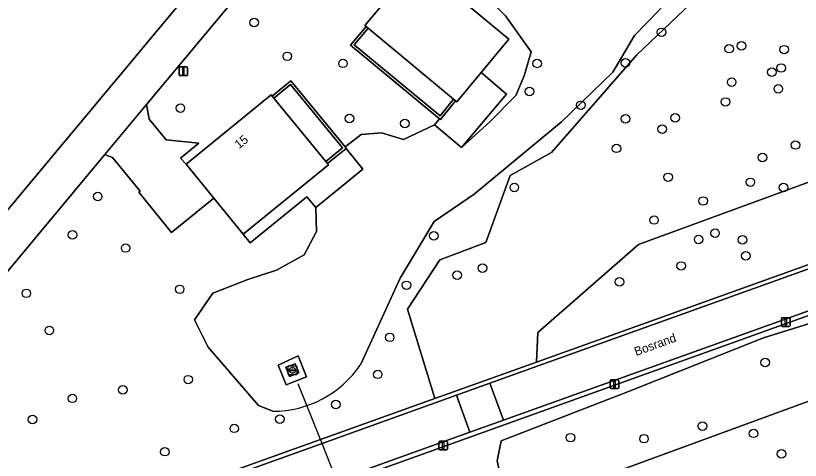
# Model space of a CAD drawing. Extents: x 156661 to 157576, y 383570 to 384425.
# Drawn here: x 156996.3 to 157086.2, y 383757.3 to 383808.2 of the extents above; entities that cross this region are included whole.
import ezdxf

# ---------------------------------------------------------------- set-up
doc = ezdxf.new("R2010")
doc.units = 0
for name, color, linetype in [('IMGEO_Boom', 7, 'Continuous'), ('IMGEO_Duiker', 7, 'Continuous'), ('IMGEO_Erf', 7, 'Continuous'), ('IMGEO_Groenvoorziening', 7, 'Continuous'), ('IMGEO_Kolk', 7, 'Continuous'), ('IMGEO_Lichtmast', 7, 'Continuous'), ('IMGEO_Loofbos', 7, 'Continuous'), ('IMGEO_Meer_plas_ven_vijver', 7, 'Continuous'), ('IMGEO_Muur', 7, 'Continuous'), ('IMGEO_Openbare_ruimte_label', 7, 'Continuous'), ('IMGEO_Pand', 7, 'Continuous'), ('IMGEO_Pand_nummerreeks', 7, 'Continuous'), ('IMGEO_Rijbaan_lokaal_halfverhard', 7, 'Continuous'), ('IMGEO_Rijbaan_lokaal_open', 7, 'Continuous'), ('IMGEO_Terreindeel_halfverhard', 7, 'Continuous'), ('IMGEO_Terreindeel_open', 7, 'Continuous')]:
    doc.layers.add(name, color=color, linetype=linetype)

msp = doc.modelspace()

# ---------------------------------------------------------------- linework, layer by layer
at = {"layer": 'IMGEO_Boom'}
for centre in [(157023.586, 383807.399), (157070.266, 383806.274), (157078.003, 383804.396), (157079.431, 383804.722), (157027.378, 383803.523), (157084.32, 383804.288), (157033.761, 383802.717), (157056.017, 383802.713), (157066.138, 383802.772), (157082.896, 383801.711), (157083.961, 383802.188), (157078.297, 383800.559), (157083.643, 383799.808), (157055.136, 383799.494), (157077.593, 383798.295), (157015.127, 383797.576), (157061.008, 383797.913), (157034.497, 383796.409), (157066.128, 383796.361), (157071.829, 383796.469), (157040.851, 383795.831), (157070.321, 383795.171), (157065.097, 383792.979), (157085.608, 383793.361), (157081.831, 383791.924), (157071.017, 383789.666), (157080.441, 383789.096), (157053.394, 383788.501), (157084.233, 383788.488), (157005.654, 383787.467), (157075.021, 383786.954), (157069.402, 383784.773), (157002.775, 383783.072), (157044.176, 383782.955), (157076.391, 383783.263), (157074.509, 383782.544), (157079.541, 383782.504), (157008.854, 383781.564), (157079.93, 383780.668), (157049.75, 383779.249), (157072.508, 383779.515), (157046.842, 383778.451), (157065.44, 383777.699), (157015.053, 383776.838), (157041.044, 383777.301), (156997.479, 383776.378), (157000.113, 383772.115), (157039.116, 383771.338), (157082.143, 383768.453), (157037.741, 383767.098), (157016.033, 383766.494), (157008.524, 383765.317), (157002.754, 383764.348), (157032.946, 383763.648), (156998.183, 383761.932), (157026.518, 383761.972), (157074.961, 383761.159), (157021.308, 383760.914), (157080.791, 383760.337), (157059.835, 383759.848), (157068.257, 383759.732), (157013.341, 383758.239), (157084.013, 383758.006)]:
    msp.add_circle(centre, 0.489, dxfattribs=at)
at = {"layer": 'IMGEO_Duiker'}
msp.add_lwpolyline([(157036.031, 383747.459), (157035.68, 383748.34), (157035.126, 383749.729), (157033.227, 383754.492), (157033.035, 383754.973), (157031.359, 383759.177), (157031.176, 383759.637), (157028.632, 383766.018)], dxfattribs=at)
at = {"layer": 'IMGEO_Erf'}
for points in [[(157036.639, 383806.758), (157035.055, 383804.855), (157044.899, 383796.693), (157046.433, 383798.607)], [(157049.612, 383801.681), (157046.791, 383798.309), (157046.66, 383798.418), (157044.942, 383796.275), (157044.832, 383796.367), (157044.237, 383795.66), (157047.355, 383793.093), (157052.489, 383799.189)], [(157025.835, 383798.749), (157031.798, 383791.459), (157033.713, 383793.026), (157027.752, 383800.314)], [(157015.787, 383791.168), (157015.141, 383791.863), (157017.237, 383793.583), (157013.515, 383793.948), (157011.55, 383796.328), (157011.25, 383798.001), (157006.477, 383792.278), (157006.733, 383792.178), (157007.366, 383791.931), (157010.536, 383788.085), (157010.387, 383787.957), (157014.101, 383783.353), (157018.957, 383787.281)], [(157034.129, 383792.985), (157031.985, 383791.231), (157032.093, 383791.1), (157022.328, 383783.148), (157023.125, 383782.171), (157029.603, 383787.444), (157030.634, 383786.19), (157036.05, 383790.598)]]:
    msp.add_lwpolyline(points, close=True, dxfattribs=at)
at = {"layer": 'IMGEO_Groenvoorziening'}
for points in [[(157001.056, 383748.839), (157031.176, 383759.637), (157044.279, 383764.335), (157041.161, 383774.554), (157044.855, 383780.228), (157050.132, 383782.207), (157052.903, 383789.859), (157057.653, 383792.498), (157067.416, 383803.713), (157075.201, 383811.102), (157078.499, 383816.907), (157083.249, 383825.483), (157079.423, 383827.99), (157075.729, 383832.476), (157070.319, 383836.83), (157065.701, 383839.6), (157058.84, 383842.107), (157053.931, 383851.225)], [(156977.657, 383765.109), (156984.098, 383772.514), (157042.748, 383842.776), (157045.986, 383846.984)], [(157033.585, 383824.777), (157011.25, 383798.001), (157011.55, 383796.328), (157013.515, 383793.948), (157017.237, 383793.583), (157015.141, 383791.863), (157015.787, 383791.168), (157025.541, 383799.109), (157025.648, 383798.977), (157027.792, 383800.731), (157033.993, 383793.151), (157035.856, 383794.566), (157038.179, 383794.751), (157040.685, 383794.008), (157044.237, 383795.66), (157044.832, 383796.367), (157034.639, 383804.817), (157036.412, 383806.947), (157036.281, 383807.055), (157038.979, 383810.3)], [(157048.157, 383809.325), (157052.782, 383805.471), (157049.612, 383801.681), (157052.489, 383799.189), (157047.355, 383793.093), (157050.592, 383796.034), (157053.555, 383799.055), (157054.51, 383801.302), (157055.329, 383804.054), (157052.364, 383808.162), (157049.338, 383811.217)], [(157069.849, 383808.66), (157067.156, 383805.908), (157064.689, 383801.724), (157058.8, 383796.028), (157048.793, 383787.718), (157044.191, 383784.604), (157040.328, 383778.097), (157035.789, 383768.247)], [(157025.724, 383762.875), (157024.08, 383763.536), (157018.316, 383770.225), (157016.738, 383773.33), (157018.834, 383776.415), (157022.847, 383777.972), (157026.157, 383779.026), (157029.299, 383780.778), (157030.738, 383783.441), (157030.634, 383786.19), (157029.603, 383787.444), (157023.125, 383782.171), (157022.328, 383783.148), (157018.957, 383787.281), (157014.101, 383783.353), (157010.387, 383787.957), (157010.536, 383788.085), (157007.366, 383791.931), (157006.733, 383792.178), (157006.477, 383792.278), (156988.102, 383770.249), (156980.924, 383761.917)], [(157081.943, 383771.284), (157107.824, 383779.345), (157107.188, 383781.072), (157033.227, 383754.492), (157001.66, 383743.148)], [(156796.698, 383685.325), (156797.724, 383682.959), (156953.889, 383739.271), (157002.627, 383740.411), (157034.818, 383750.499), (157051.726, 383755.797), (157051.41, 383757.175), (157051.892, 383759.471), (157066.467, 383765.117), (157081.943, 383771.284)]]:
    msp.add_lwpolyline(points, dxfattribs=at)
for points in [[(157104.049, 383785.763), (157100.642, 383794.067), (157067.612, 383781.99), (157056.08, 383771.905), (157055.927, 383768.511)], [(157114.54, 383765.376), (157111.088, 383774.197), (157108.679, 383778.966), (157108.053, 383778.722), (157107.824, 383779.345), (157081.943, 383771.284), (157066.467, 383765.117), (157051.892, 383759.471), (157051.41, 383757.175), (157051.726, 383755.797), (157052.724, 383751.446), (157102.46, 383769.641), (157103.234, 383774.689), (157106.931, 383776.487), (157108.251, 383771.85), (157111.439, 383764.518)]]:
    msp.add_lwpolyline(points, close=True, dxfattribs=at)
msp.add_arc((157025.747, 383774.946), 12.071, 269.88907, 326.29135, dxfattribs=at)
at = {"layer": 'IMGEO_Kolk'}
for p, q in [((157027.468, 383767.132), (157027.468, 383767.984)), ((157027.543, 383768.058), (157028.395, 383768.058)), ((157028.469, 383767.984), (157028.469, 383767.132)), ((157028.395, 383767.058), (157027.543, 383767.058)), ((157027.727, 383767.552), (157027.727, 383767.564)), ((157028.165, 383767.515), (157027.767, 383767.515)), ((157027.77, 383767.601), (157028.168, 383767.601)), ((157027.979, 383767.278), (157027.954, 383767.278)), ((157027.956, 383767.838), (157027.981, 383767.838)), ((157028.211, 383767.564), (157028.211, 383767.552))]:
    msp.add_line(p, q, dxfattribs=at)
for points in [[(157027.468, 383767.132), (157027.468, 383767.984)], [(157027.543, 383768.058), (157028.395, 383768.058)], [(157028.469, 383767.984), (157028.469, 383767.132)], [(157028.395, 383767.058), (157027.543, 383767.058)]]:
    msp.add_lwpolyline(points, dxfattribs=at)
for centre, radius, start, end in [((157027.545, 383767.982), 0.0765, 91.55205, 178.44795), ((157027.545, 383767.982), 0.0765, 91.55205, 178.44795), ((157028.393, 383767.982), 0.0765, 1.55205, 88.44795), ((157028.393, 383767.982), 0.0765, 1.55205, 88.44795), ((157027.545, 383767.134), 0.0765, 181.55205, 268.44795), ((157027.545, 383767.134), 0.0765, 181.55205, 268.44795), ((157027.767, 383767.561), 0.0403, 85.87752, 175.75265), ((157027.764, 383767.551), 0.0366, 178.93798, 274.71019), ((157028.168, 383767.558), 0.043, 264.86636, 352.45326), ((157028.172, 383767.563), 0.0386, 1.73085, 96.63898), ((157028.393, 383767.134), 0.0765, 271.55205, 358.44795), ((157028.393, 383767.134), 0.0765, 271.55205, 358.44795)]:
    msp.add_arc(centre, radius, start, end, dxfattribs=at)
for centre, major_axis, ratio, start_param, end_param in [((157027.955, 383767.558), (-0.387, 0.002), 0.722429, 4.712389, 7.853982), ((157027.98, 383767.558), (-0.39, 0.002), 0.717154, 1.570796, 4.712389)]:
    msp.add_ellipse(centre, major_axis=major_axis, ratio=ratio, start_param=start_param, end_param=end_param, dxfattribs=at)
at = {"layer": 'IMGEO_Lichtmast'}
for p, q in [((157014.972, 383801.416), (157014.972, 383802.216)), ((157014.972, 383802.216), (157014.972, 383801.416)), ((157015.072, 383802.316), (157015.862, 383802.316)), ((157015.862, 383802.316), (157015.072, 383802.316)), ((157015.962, 383802.216), (157015.962, 383801.416)), ((157015.962, 383801.416), (157015.962, 383802.216)), ((157015.862, 383801.316), (157015.072, 383801.316)), ((157015.072, 383801.316), (157015.862, 383801.316)), ((157083.993, 383772.69), (157083.993, 383773.49)), ((157083.993, 383773.49), (157083.993, 383772.69)), ((157084.093, 383773.59), (157084.883, 383773.59)), ((157084.883, 383773.59), (157084.093, 383773.59)), ((157084.983, 383773.49), (157084.983, 383772.69)), ((157084.983, 383772.69), (157084.983, 383773.49)), ((157084.883, 383772.59), (157084.093, 383772.59)), ((157084.093, 383772.59), (157084.883, 383772.59)), ((157064.361, 383765.572), (157064.361, 383766.372)), ((157064.361, 383766.372), (157064.361, 383765.572)), ((157064.461, 383766.472), (157065.251, 383766.472)), ((157065.251, 383766.472), (157064.461, 383766.472)), ((157065.351, 383766.372), (157065.351, 383765.572)), ((157065.351, 383765.572), (157065.351, 383766.372)), ((157065.251, 383765.472), (157064.461, 383765.472)), ((157064.461, 383765.472), (157065.251, 383765.472)), ((157044.755, 383758.548), (157044.755, 383759.348)), ((157044.755, 383759.348), (157044.755, 383758.548)), ((157044.855, 383759.448), (157045.645, 383759.448)), ((157045.645, 383759.448), (157044.855, 383759.448)), ((157045.745, 383759.348), (157045.745, 383758.548)), ((157045.745, 383758.548), (157045.745, 383759.348)), ((157045.645, 383758.448), (157044.855, 383758.448)), ((157044.855, 383758.448), (157045.645, 383758.448))]:
    msp.add_line(p, q, dxfattribs=at)
for points in [[(157015.392, 383802.191), (157015.542, 383802.191), (157015.542, 383801.441), (157015.392, 383801.441), (157015.392, 383802.191)], [(157084.413, 383773.465), (157084.563, 383773.465), (157084.563, 383772.715), (157084.413, 383772.715), (157084.413, 383773.465)], [(157064.781, 383766.347), (157064.931, 383766.347), (157064.931, 383765.597), (157064.781, 383765.597), (157064.781, 383766.347)], [(157045.175, 383759.323), (157045.325, 383759.323), (157045.325, 383758.573), (157045.175, 383758.573), (157045.175, 383759.323)]]:
    msp.add_lwpolyline(points, dxfattribs=at)
for centre, start, end in [((157015.072, 383802.216), 90, 180), ((157015.072, 383802.216), 90, 180), ((157015.862, 383802.216), 0, 90), ((157015.862, 383802.216), 360, 90), ((157015.072, 383801.416), 180, 270), ((157015.072, 383801.416), 180, 270), ((157015.862, 383801.416), 270, 0), ((157015.862, 383801.416), 270, 0), ((157084.093, 383773.49), 90, 180), ((157084.093, 383773.49), 90, 180), ((157084.883, 383773.49), 0, 90), ((157084.883, 383773.49), 360, 90), ((157084.093, 383772.69), 180, 270), ((157084.093, 383772.69), 180, 270), ((157084.883, 383772.69), 270, 0), ((157084.883, 383772.69), 270, 0), ((157064.461, 383766.372), 90, 180), ((157064.461, 383766.372), 90, 180), ((157065.251, 383766.372), 0, 90), ((157065.251, 383766.372), 360, 90), ((157064.461, 383765.572), 180, 270), ((157064.461, 383765.572), 180, 270), ((157065.251, 383765.572), 270, 0), ((157065.251, 383765.572), 270, 0), ((157044.855, 383759.348), 90, 180), ((157044.855, 383759.348), 90, 180), ((157045.645, 383759.348), 0, 90), ((157045.645, 383759.348), 360, 90), ((157044.855, 383758.548), 180, 270), ((157044.855, 383758.548), 180, 270), ((157045.645, 383758.548), 270, 0), ((157045.645, 383758.548), 270, 0)]:
    msp.add_arc(centre, 0.1, start, end, dxfattribs=at)
at = {"layer": 'IMGEO_Loofbos'}
for points in [[(157053.931, 383851.225), (157058.84, 383842.107), (157065.701, 383839.6), (157070.319, 383836.83), (157075.729, 383832.476), (157079.423, 383827.99), (157083.249, 383825.483), (157078.499, 383816.907), (157075.201, 383811.102), (157067.416, 383803.713), (157057.653, 383792.498), (157052.903, 383789.859), (157050.132, 383782.207), (157044.855, 383780.228), (157041.161, 383774.554), (157044.279, 383764.335), (157055.927, 383768.511), (157056.08, 383771.905), (157067.612, 383781.99), (157100.642, 383794.067), (157104.049, 383785.763), (157100.533, 383804.768)], [(157115.167, 383763.775), (157114.54, 383765.376), (157111.439, 383764.518), (157108.251, 383771.85), (157106.931, 383776.487), (157103.234, 383774.689), (157102.46, 383769.641), (157052.724, 383751.446), (157051.726, 383755.797), (157034.818, 383750.499), (157002.627, 383740.411), (156953.889, 383739.271), (156797.724, 383682.959)]]:
    msp.add_lwpolyline(points, dxfattribs=at)
at = {"layer": 'IMGEO_Meer_plas_ven_vijver'}
for points in [[(157035.789, 383768.247), (157040.328, 383778.097), (157044.191, 383784.604), (157048.793, 383787.718), (157058.8, 383796.028), (157064.689, 383801.724), (157067.156, 383805.908), (157069.849, 383808.66), (157073.495, 383812.613)], [(157049.338, 383811.217), (157052.364, 383808.162), (157055.329, 383804.054), (157054.51, 383801.302), (157053.555, 383799.055), (157050.592, 383796.034), (157047.355, 383793.093), (157044.237, 383795.66), (157040.685, 383794.008), (157038.179, 383794.751), (157035.856, 383794.566), (157033.993, 383793.151), (157034.129, 383792.985), (157036.05, 383790.598), (157030.634, 383786.19), (157030.738, 383783.441), (157029.299, 383780.778), (157026.157, 383779.026), (157022.847, 383777.972), (157018.834, 383776.415), (157016.738, 383773.33), (157018.316, 383770.225), (157024.08, 383763.536), (157025.724, 383762.875)]]:
    msp.add_lwpolyline(points, dxfattribs=at)
msp.add_lwpolyline([(157028.606, 383769.202), (157029.582, 383766.823), (157027.238, 383765.909), (157026.349, 383768.166)], close=True, dxfattribs=at)
msp.add_arc((157025.747, 383774.946), 12.071, 269.88907, 326.29135, dxfattribs=at)
at = {"layer": 'IMGEO_Muur'}
for points in [[(157036.639, 383806.758), (157036.412, 383806.947), (157034.639, 383804.817), (157044.832, 383796.367), (157044.942, 383796.275), (157046.66, 383798.418), (157046.433, 383798.607), (157044.899, 383796.693), (157035.055, 383804.855)], [(157027.752, 383800.314), (157033.713, 383793.026), (157031.798, 383791.459), (157031.985, 383791.231), (157034.129, 383792.985), (157033.993, 383793.151), (157027.792, 383800.731), (157025.648, 383798.977), (157025.835, 383798.749)]]:
    msp.add_lwpolyline(points, close=True, dxfattribs=at)
at = {"layer": 'IMGEO_Pand'}
for points in [[(157052.782, 383805.471), (157048.157, 383809.325), (157042.256, 383814.242), (157038.979, 383810.3), (157036.281, 383807.055), (157036.412, 383806.947), (157036.639, 383806.758), (157046.433, 383798.607), (157046.66, 383798.418), (157046.791, 383798.309), (157049.612, 383801.681)], [(157025.835, 383798.749), (157025.648, 383798.977), (157025.541, 383799.109), (157015.787, 383791.168), (157018.957, 383787.281), (157022.328, 383783.148), (157032.093, 383791.1), (157031.985, 383791.231), (157031.798, 383791.459)]]:
    msp.add_lwpolyline(points, close=True, dxfattribs=at)
at = {"layer": 'IMGEO_Rijbaan_lokaal_halfverhard'}
for points in [[(157105.539, 383785.799), (157105.384, 383786.242), (157104.143, 383785.797), (157104.049, 383785.763), (157055.927, 383768.511), (157044.279, 383764.335), (157031.176, 383759.637), (157001.056, 383748.839)], [(157001.245, 383748.37), (157031.359, 383759.177), (157046.769, 383764.708), (157050.584, 383766.077), (157105.539, 383785.799)], [(157107.188, 383781.072), (157107.022, 383781.522), (157052.149, 383761.837), (157048.312, 383760.46), (157033.035, 383754.973), (157001.503, 383743.647)], [(157001.66, 383743.148), (157033.227, 383754.492), (157107.188, 383781.072)]]:
    msp.add_lwpolyline(points, dxfattribs=at)
at = {"layer": 'IMGEO_Rijbaan_lokaal_open'}
for points in [[(157045.986, 383846.984), (157042.748, 383842.776), (156984.098, 383772.514), (156977.657, 383765.109)], [(156980.924, 383761.917), (156988.102, 383770.249), (157006.477, 383792.278), (157011.25, 383798.001), (157033.585, 383824.777), (157037.526, 383829.502), (157045.278, 383838.796)], [(157115.632, 383788.221), (157110.913, 383787.159), (157106.349, 383786.004), (157106.688, 383785.066), (157105.907, 383784.74), (157105.539, 383785.799), (157050.584, 383766.077), (157052.149, 383761.837), (157107.022, 383781.522)], [(157001.503, 383743.647), (157033.035, 383754.973), (157048.312, 383760.46), (157046.769, 383764.708), (157031.359, 383759.177), (157001.245, 383748.37)]]:
    msp.add_lwpolyline(points, dxfattribs=at)
msp.add_lwpolyline([(157050.584, 383766.077), (157046.769, 383764.708), (157048.312, 383760.46), (157052.149, 383761.837)], close=True, dxfattribs=at)
at = {"layer": 'IMGEO_Terreindeel_halfverhard'}
for points in [[(157028.606, 383769.202), (157026.349, 383768.166), (157027.238, 383765.909), (157029.582, 383766.823)], [(157027.207, 383767.909), (157028.272, 383768.317), (157028.693, 383767.268), (157027.641, 383766.839)]]:
    msp.add_lwpolyline(points, close=True, dxfattribs=at)
at = {"layer": 'IMGEO_Terreindeel_open'}
msp.add_lwpolyline([(157028.272, 383768.317), (157027.207, 383767.909), (157027.641, 383766.839), (157028.693, 383767.268)], close=True, dxfattribs=at)

# ---------------------------------------------------------------- texts
at = {"layer": 'IMGEO_Openbare_ruimte_label'}
msp.add_text('Bosrand', height=1, rotation=19.81181, dxfattribs=at).set_placement((157067.351, 383769.193))
at = {"layer": 'IMGEO_Pand_nummerreeks'}
msp.add_text('15', height=1, rotation=39.15021, dxfattribs=at).set_placement((157021.848, 383792.879))

doc.saveas('drawing.dxf')
